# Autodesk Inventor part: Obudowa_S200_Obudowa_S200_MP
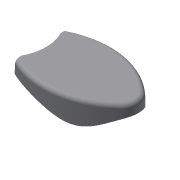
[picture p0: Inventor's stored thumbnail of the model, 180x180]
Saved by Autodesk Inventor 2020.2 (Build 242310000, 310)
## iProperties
Created: 2015-02
Part Number: Obudowa_S200_Obudowa_S200_MP
Material: Ogólny
Document SubType Name: Modeling
Designer: F.Stasiak
Density: 1 g/cm^3
Appearance: Domyślna
Catalog Web Link: www.expertbooks.pl
Manager: www.cadconsulting.pl
Company: Fabian Stasiak CAD Consulting
Author: F.Stasiak
Subject: Zbiór ćwiczeń. Autodesk Inventor 2020. Kurs Professional
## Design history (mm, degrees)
derived "Obudowa_S200.ipt"
node "Obudowa_S200_Obudowa_S200_WP"
feature "Bryła1::Obudowa_S200.ipt"
tag "Bryła wyprowadzona1"
feature "Bryła1::Obudowa_S200_Obudowa_S200_WP"
tag "Bryła wyprowadzona2"
node "Bryła1"
feature "Obudowa_S200.ipt_Bodies"
node "Bryła2"
feature "Obudowa_S200_Obudowa_S200_WP_Bodies"
other parameters: "d1" = 85, "d2" = 85, "d3" = 59, "d4" = 59, "d6" = 0, "Xmin" = -85, "Ymin" = -59, "Xmax" = 85, "Ymax" = 59
